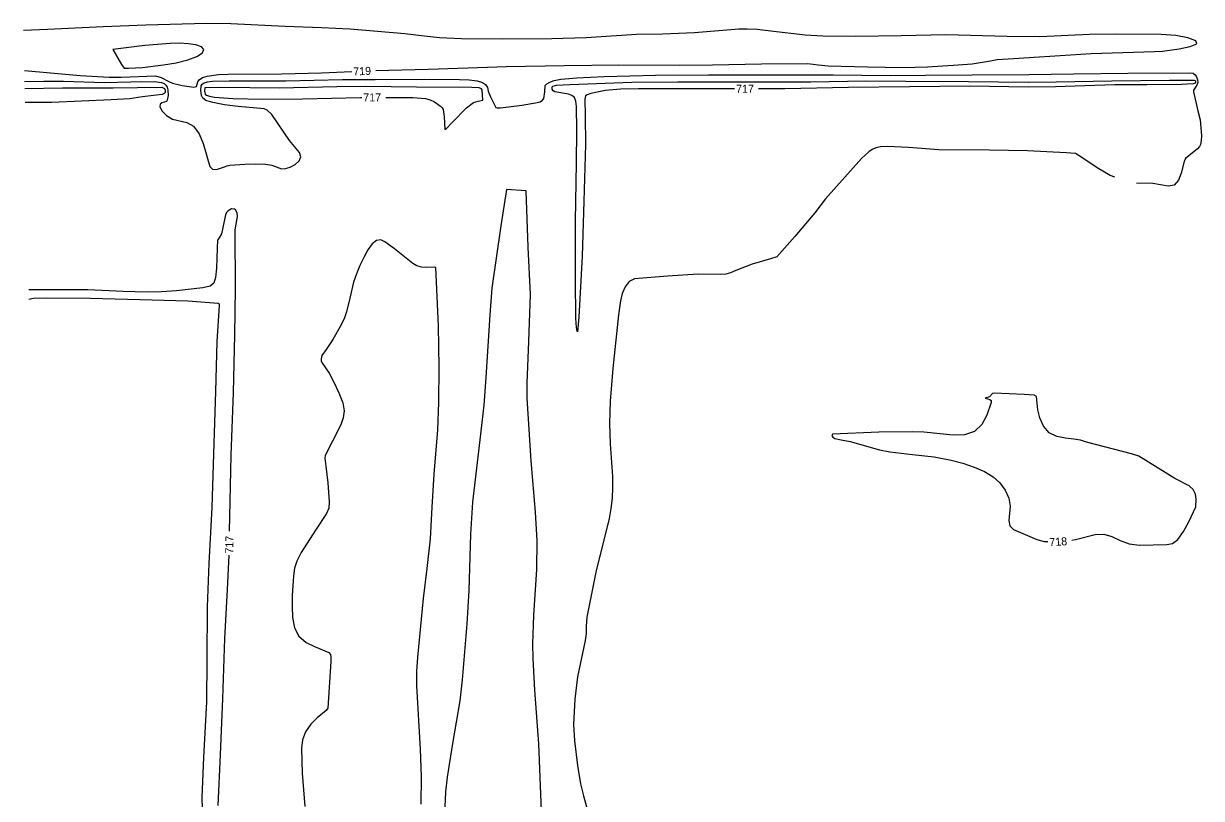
# Model space of a CAD drawing. Extents: x -310467766 to 17062430, y -322263100 to 8322522.
# Drawn here: x 1397523 to 1398112, y 573479 to 573867 of the extents above; entities that cross this region are included whole.
import ezdxf

# ---------------------------------------------------------------- set-up
doc = ezdxf.new("R2010")
doc.units = 0
doc.layers.add('DT_X_Contour_Minor', color=7, linetype='Continuous')
doc.layers.add('Level 19', color=7, linetype='Continuous')

msp = doc.modelspace()

# ---------------------------------------------------------------- linework, layer by layer
at = {"layer": 'DT_X_Contour_Minor'}
for points in [[(1397699.48, 573843.04), (1397725.75, 573843.69), (1397755.3, 573844.71), (1397764.75, 573845.01), (1397793.79, 573845.5), (1397821.02, 573845.9), (1397851.36, 573845.78), (1397867.89, 573845.89), (1397892.37, 573846.36), (1397915.31, 573846.63), (1397918.22, 573846.18), (1397920.58, 573845.83), (1397925.72, 573845.45), (1397945.29, 573844.83), (1397963, 573844.63), (1397975.33, 573844.98), (1397990.69, 573845.83), (1397997.71, 573846.46), (1398006.82, 573847.94), (1398010.21, 573848.53), (1398018.36, 573849.1), (1398031.26, 573849.87), (1398057.17, 573851.5), (1398088.83, 573852.55), (1398092.84, 573852.79), (1398101.06, 573853.93), (1398106.55, 573855.01), (1398109.94, 573856.38), (1398109.42, 573857.97), (1398105.53, 573859.49), (1398099.42, 573860.62), (1398092.15, 573861.15), (1398070.03, 573861.24), (1398056.32, 573861.13), (1398031.5, 573859.97), (1398015.11, 573860.04), (1397984.53, 573860.83), (1397962.23, 573860.43), (1397939.36, 573860.03), (1397922.95, 573860.26), (1397914.24, 573860.81), (1397896.95, 573862.74), (1397890.09, 573863.52), (1397885.23, 573863.82), (1397881.03, 573863.68), (1397858.88, 573861.93), (1397842.91, 573861.25), (1397829.91, 573861), (1397804.71, 573859.47), (1397787.57, 573858.89), (1397763.03, 573858.78), (1397742.33, 573858.95), (1397731.31, 573859.42), (1397722.43, 573860.36), (1397714.1, 573861.42), (1397686.62, 573863.82), (1397672.37, 573864.42), (1397654.18, 573865.01), (1397627.05, 573866.47), (1397614.95, 573866.55), (1397584.57, 573865.76), (1397563.28, 573864.94), (1397535.45, 573863.62), (1397523.43, 573863.03)], [(1397573.77, 573844.31), (1397575.93, 573844.21), (1397582.87, 573844.6), (1397593.34, 573845.83), (1397599.67, 573846.93), (1397605.5, 573848.36), (1397610.01, 573850.11), (1397612.81, 573851.95), (1397613.63, 573853.64), (1397612.37, 573854.95), (1397609.52, 573855.89), (1397605.74, 573856.45), (1397601.5, 573856.68), (1397596.66, 573856.58), (1397584.13, 573855.51), (1397568.04, 573853.56), (1397572.44, 573846.03), (1397573.77, 573844.31)], [(1397523.83, 573843), (1397551.67, 573840.54), (1397566.15, 573839.7), (1397572.23, 573839.81), (1397589.36, 573840.39), (1397592.23, 573839.52), (1397595.98, 573837.61), (1397597.96, 573836.72), (1397602.68, 573835.62), (1397608.54, 573834.8), (1397609.84, 573835.13), (1397610.19, 573836.31), (1397610.51, 573837.33), (1397611.28, 573838.47), (1397612.82, 573839.51), (1397615.27, 573840.28), (1397620.91, 573841.08), (1397625.75, 573841.27), (1397652.54, 573841.37), (1397672.35, 573841.91), (1397687.49, 573842.55)], [(1397523.94, 573837.63), (1397533.61, 573837.78), (1397543.38, 573837.74), (1397563.86, 573837.03), (1397577.12, 573837.33), (1397588.91, 573837.64), (1397592.39, 573837.1), (1397593.66, 573836.52), (1397594.61, 573835.72), (1397595.24, 573834.68), (1397595.6, 573833.45), (1397595.66, 573830.61), (1397595.19, 573828.23), (1397594.87, 573827.66), (1397593.64, 573827.23), (1397592.59, 573826.92), (1397591.71, 573826.23), (1397591.61, 573824.9), (1397592.71, 573822.82), (1397594.9, 573820.54), (1397597.91, 573818.77), (1397605.1, 573817.08), (1397608.44, 573815.17), (1397611.14, 573811.42), (1397613.17, 573806.55), (1397616.57, 573795.12), (1397617.88, 573793.72), (1397619.82, 573793.57), (1397623.88, 573794.96), (1397625.14, 573795.44), (1397626.6, 573795.69), (1397634.01, 573796.17), (1397639.53, 573796.37), (1397644.4, 573796.29), (1397647.49, 573795.77), (1397652.32, 573793.96), (1397654.36, 573794.05), (1397656.7, 573794.74), (1397659.18, 573796.1), (1397661.21, 573797.92), (1397662.09, 573799.97), (1397661.35, 573802.12), (1397656.45, 573808.12), (1397647.46, 573821.09), (1397645.28, 573823.17), (1397643.67, 573823.92), (1397630.72, 573825.1), (1397623.91, 573825.97), (1397618.04, 573827), (1397614.54, 573828.12), (1397612.98, 573829.32), (1397612.45, 573830.57), (1397612.07, 573833.14), (1397612.24, 573835.36), (1397612.71, 573836.22), (1397613.67, 573836.9), (1397615.31, 573837.38), (1397617.83, 573837.68), (1397626.25, 573837.88), (1397654.52, 573837.86), (1397682.93, 573838.54), (1397699.24, 573838.59), (1397723.67, 573838.67), (1397741.34, 573838.61), (1397746.17, 573838.41), (1397750.22, 573837.92), (1397752.85, 573837.07), (1397754.28, 573836.1), (1397755.41, 573834.52), (1397755.67, 573832.8), (1397756.85, 573829.93), (1397759.54, 573824.6), (1397760.23, 573824.42), (1397761.89, 573824.45), (1397772.57, 573825.81), (1397779.37, 573826.85), (1397781.63, 573827.46), (1397782.9, 573828.2), (1397783.46, 573829.1), (1397783.95, 573832.4), (1397784.25, 573835.55), (1397785.01, 573836.39), (1397786.44, 573837.29), (1397788.75, 573838.09), (1397792.02, 573838.69), (1397800.06, 573839.42), (1397813.71, 573840.01), (1397839.31, 573840.71), (1397865.81, 573840.92), (1397897.2, 573840.84), (1397928.21, 573840.87), (1397956.81, 573840.65), (1397974.33, 573840.76), (1397997.62, 573840.99), (1398025.93, 573841.12), (1398048.26, 573841.43), (1398075.52, 573841.77), (1398106.86, 573841.99), (1398108.06, 573841.67), (1398109.06, 573840.99), (1398109.87, 573839.85)], [(1398109.87, 573839.85), (1398110.38, 573838.43), (1398110.44, 573837), (1398109.99, 573835.74), (1398108.31, 573833.21), (1398108.33, 573832.38), (1398110.5, 573822.94), (1398111.68, 573818.42), (1398112.27, 573810.66), (1398112.17, 573807.9), (1398111.77, 573806.11), (1398111.27, 573805.04), (1398110.28, 573803.85), (1398104.26, 573799.01), (1398103.65, 573797.54), (1398102.17, 573791.76), (1398100.76, 573788.17), (1398098.63, 573785.7), (1398095.67, 573785.19), (1398088.01, 573786.66), (1398079.86, 573786.74)], [(1397524.01, 573834.09), (1397542.84, 573834.41), (1397568.29, 573834.44), (1397592.55, 573834.72), (1397593.86, 573834.16), (1397594.26, 573833.23), (1397594.23, 573832.07), (1397593.8, 573831.51), (1397592.74, 573831.08), (1397588.39, 573830.6), (1397582.9, 573829.89), (1397576.4, 573828.93), (1397567.29, 573828.43), (1397537.58, 573827.12), (1397532.63, 573827), (1397524.15, 573827.14)], [(1397704.48, 573829.63), (1397718, 573829.66), (1397724.34, 573829.1), (1397726.75, 573828.43), (1397728.84, 573827.44), (1397731.92, 573825.28), (1397732.77, 573824.47), (1397733.24, 573823.58), (1397733.63, 573820.09), (1397733.96, 573813.61), (1397734.45, 573813.83), (1397737.68, 573817.12), (1397744.93, 573824.49), (1397748.3, 573827.02), (1397750.7, 573827.79), (1397753.02, 573828.28), (1397752.73, 573833.44), (1397752.42, 573833.87), (1397751.17, 573834.43), (1397747.57, 573834.64), (1397719.86, 573834.69), (1397694.59, 573835.1), (1397680.06, 573834.92), (1397651.27, 573834.27), (1397621.98, 573834.6), (1397614.12, 573834.4), (1397613.87, 573832.75), (1397614.24, 573831.19), (1397614.88, 573830.7), (1397616.31, 573830.24), (1397618.87, 573829.82), (1397628.15, 573829.15), (1397642.67, 573828.82), (1397662.83, 573828.95), (1397691.93, 573829.59), (1397692.48, 573829.59)], [(1397878.89, 573833.94), (1397874.82, 573833.94), (1397857.2, 573833.98), (1397830.81, 573833.96), (1397821.94, 573833.82), (1397814.16, 573833.01), (1397807.01, 573831.63), (1397805.16, 573830.99), (1397804.36, 573830.36), (1397804.05, 573828.71), (1397804.16, 573820.44), (1397804.27, 573806.07), (1397803.5, 573777.68), (1397802.64, 573750.2), (1397801.05, 573719.7), (1397800.4, 573712.51), (1397800.12, 573712.77), (1397799.79, 573714.54), (1397799.53, 573719.34), (1397799.39, 573738.61), (1397799.35, 573767.89), (1397799.78, 573796.83), (1397800.04, 573813.3), (1397799.82, 573825.09), (1397799.5, 573827.67), (1397798.78, 573829.51), (1397797.49, 573830.62), (1397795.8, 573831.2), (1397789.01, 573832.35), (1397788.12, 573832.96), (1397787.64, 573833.68), (1397787.61, 573834.87), (1397788.01, 573835.24), (1397789.88, 573835.69), (1397796.47, 573836.07), (1397827.44, 573837.18), (1397850.52, 573837.39), (1397883.7, 573837.44), (1397917.03, 573837.37), (1397944.52, 573837.89), (1397964.55, 573837.69), (1397995.75, 573837.51), (1398025.92, 573837.2), (1398039.56, 573837.39), (1398067.42, 573837.88), (1398096.24, 573838.25), (1398108.71, 573838.28), (1398109.25, 573837.83), (1398109.35, 573837.11), (1398109.09, 573836.76), (1398108.13, 573836.45), (1398102.22, 573836.06), (1398085, 573835.96), (1398069.03, 573835.85), (1398053.94, 573835.34), (1398039.27, 573834.83), (1398025.71, 573834.82), (1397996.67, 573835.18), (1397966.24, 573834.85), (1397935.86, 573834.59), (1397904.01, 573833.96), (1397890.89, 573833.95)], [(1398068.9, 573789.7), (1398066.71, 573790.64), (1398060.22, 573794.34), (1398051.95, 573799.88), (1398049.27, 573801.62), (1398044.7, 573801.94), (1398025.24, 573802.94), (1398006.28, 573803.19), (1397981.04, 573803.34), (1397974.41, 573803.86), (1397965.88, 573804.66), (1397955.29, 573805.13), (1397951.77, 573804.92), (1397949.43, 573804.38), (1397947.69, 573803.56), (1397946.04, 573802.47), (1397942.28, 573799.03), (1397924.25, 573778.94), (1397919.07, 573771.99), (1397908.97, 573760.08), (1397900.06, 573749.97), (1397896.82, 573748.94), (1397887.71, 573746.18), (1397879.48, 573743.11), (1397876.87, 573741.98), (1397874.56, 573741.29), (1397872.03, 573741.09), (1397860.7, 573741.22), (1397845.28, 573740.3), (1397828.84, 573738.96), (1397826.12, 573737.53), (1397824.1, 573734.94), (1397822.7, 573731.56), (1397821.77, 573727.97), (1397820.77, 573720.96), (1397817.99, 573694.05), (1397816.73, 573677.82), (1397816.33, 573666.63), (1397816.66, 573656.36), (1397817.8, 573640.16), (1397817.91, 573634.59), (1397817.65, 573629.23), (1397817.04, 573624.06), (1397816.1, 573619.07), (1397809.54, 573592.31), (1397805.07, 573569.86), (1397804.62, 573565.34), (1397804.64, 573561.56), (1397804.15, 573558.05), (1397800.37, 573539.96), (1397799.02, 573528.85), (1397798.43, 573516.21), (1397798.84, 573507.96), (1397800.4, 573495.64), (1397801.93, 573486.41), (1397803.38, 573480.42), (1397809.49, 573458.2)], [(1397782.42, 573473.04), (1397781.04, 573506.43), (1397779.06, 573533.31), (1397778.13, 573549.13), (1397778.05, 573556.42), (1397778.6, 573570.83), (1397780.09, 573593.66), (1397780.18, 573608.11), (1397779.34, 573622.21), (1397777.18, 573647.99), (1397775.11, 573679.32), (1397775.12, 573686.77), (1397775.95, 573707.65), (1397776.93, 573731.07), (1397775.73, 573754.81), (1397774.75, 573782.91), (1397764.81, 573783.52), (1397762.03, 573765.4), (1397757.57, 573734.24), (1397756.49, 573720.95), (1397754.47, 573689.67), (1397753.53, 573675.82), (1397751.54, 573658.49), (1397747.82, 573627.25), (1397746.8, 573611.26), (1397745.98, 573583.18), (1397745.03, 573566.37), (1397742.77, 573538.5), (1397741.48, 573527.91), (1397737.91, 573506.69), (1397735.13, 573489.78), (1397734.41, 573482.53), (1397733.61, 573463.94)], [(1397626.44, 573612.81), (1397626.71, 573627.53), (1397627.21, 573650.74), (1397628.31, 573682.07), (1397629.03, 573710.93), (1397629.42, 573733.89), (1397629.15, 573763.36), (1397629.63, 573766.25), (1397630.38, 573770.01), (1397630.18, 573772), (1397629.43, 573773.37), (1397628.84, 573773.76), (1397627.31, 573773.84), (1397625.66, 573772.98), (1397624.94, 573772.12), (1397624.4, 573770.89), (1397622.36, 573761.49), (1397621.2, 573759.35), (1397620.32, 573758.18), (1397620.16, 573754.19), (1397619.85, 573744.29), (1397619.42, 573739.67), (1397618.55, 573736.81), (1397616.64, 573735.33), (1397612.99, 573734.49), (1397599.96, 573732.92), (1397592.35, 573732.38), (1397585.22, 573732.19), (1397573.16, 573732.53), (1397555.55, 573733.45), (1397530.53, 573733.43), (1397526.05, 573733.47)], [(1397722.23, 573476.31), (1397722.38, 573489.92), (1397721.89, 573503.78), (1397720.09, 573535.44), (1397720.11, 573542.68), (1397720.54, 573549.75), (1397723.43, 573579.12), (1397725.13, 573594.1), (1397726.83, 573608.97), (1397727.71, 573624.78), (1397728.72, 573641.3), (1397730.45, 573663.52), (1397730.96, 573677.13), (1397731.25, 573694.77), (1397730.87, 573715.49), (1397729.45, 573744.58), (1397728.95, 573744.8), (1397724.67, 573744.55), (1397722.36, 573744.78), (1397720.06, 573745.44), (1397718, 573746.63), (1397708.89, 573753.9), (1397704.08, 573757.38), (1397701.95, 573758.36), (1397699.87, 573758.14), (1397697.73, 573756.38), (1397695.58, 573753.38), (1397693.5, 573749.66), (1397691.55, 573745.64), (1397689.82, 573741.49), (1397688.42, 573737.3), (1397686.56, 573729.27), (1397684.95, 573722.46), (1397683.81, 573719.35), (1397682.25, 573716.01), (1397677.98, 573708.53), (1397674.65, 573703.59), (1397672.47, 573700.6), (1397672.13, 573698.94), (1397672.17, 573698), (1397672.49, 573697.07), (1397676.15, 573691.73), (1397678.58, 573687.29), (1397681.09, 573682.01), (1397682.96, 573676.94), (1397683.66, 573672.88), (1397683.25, 573669.43), (1397681.96, 573665.89), (1397677.93, 573657.72), (1397674.23, 573650.61), (1397674.05, 573649.33), (1397674.56, 573645.22), (1397675.61, 573637), (1397676.23, 573627.5), (1397675.97, 573624.36), (1397674.94, 573621.69), (1397669.41, 573613.35), (1397662.17, 573602.17), (1397660.02, 573597.86), (1397658.9, 573594.2), (1397658.33, 573590.38), (1397657.7, 573580.57), (1397657.65, 573575.05), (1397657.89, 573569.57), (1397658.84, 573564.52), (1397661.02, 573560.3), (1397664.63, 573557.18), (1397668.84, 573555.05), (1397676.02, 573552.16), (1397676.82, 573551.16), (1397677.04, 573549.97), (1397676.98, 573547.63), (1397675.62, 573524.22), (1397674.64, 573523.18), (1397670.17, 573519.39), (1397666.96, 573516.22), (1397664.29, 573512.5), (1397662.85, 573508.49), (1397662.39, 573504.32), (1397662.63, 573491.73), (1397663.34, 573483.4), (1397664.11, 573475.21)], [(1397526.14, 573728.83), (1397528.38, 573729.18), (1397535.11, 573729.49), (1397556.82, 573729.31), (1397587.71, 573728.48), (1397605.55, 573727.91), (1397620.74, 573726.79), (1397621.15, 573726.48), (1397621.25, 573725.57), (1397619.97, 573707.62), (1397619.3, 573682.61), (1397618.59, 573656.71), (1397617.59, 573624.64), (1397616.1, 573596.58), (1397615.24, 573574.91), (1397615.09, 573548.63), (1397614.82, 573527.53), (1397613.35, 573499.58), (1397612.49, 573479.81), (1397613.24, 573455.05)], [(1398047.4, 573608.33), (1398049.26, 573608.64), (1398059.11, 573611.15), (1398063.44, 573611.32), (1398067.51, 573610.07), (1398071.63, 573608.1), (1398076.17, 573606.44), (1398081.33, 573605.82), (1398094.89, 573606.11), (1398097.77, 573606.59), (1398100.44, 573608.55), (1398103.24, 573612.55), (1398105.89, 573617.43), (1398109.52, 573625), (1398109.6, 573628.75), (1398109.27, 573631.31), (1398108.19, 573633.69), (1398106.05, 573635.48), (1398098.9, 573639.16), (1398080.99, 573650.22), (1398077.38, 573651.47), (1398054.79, 573657.28), (1398051.74, 573658.2), (1398048.45, 573658.85), (1398044.39, 573659.3), (1398040.03, 573660.11), (1398036.12, 573661.96), (1398033.24, 573665.29), (1398031.41, 573669.42), (1398030.48, 573673.43), (1398029.85, 573680.13), (1398028.68, 573680.8), (1398023.69, 573681.14), (1398008.69, 573681.82), (1398007.81, 573681.53), (1398006.31, 573679.95), (1398004.1, 573679.33), (1398006.56, 573678.56), (1398007.19, 573678.1), (1398007.13, 573677.03), (1398004.92, 573670.7), (1398002.49, 573666.18), (1397998.8, 573662.57), (1397993.77, 573660.91), (1397988.1, 573660.76), (1397973.54, 573662.32), (1397967.6, 573662.5), (1397950.99, 573662.2), (1397927.91, 573661.27), (1397927.55, 573660.64), (1397927.99, 573659.85), (1397929.01, 573659.18), (1397932.11, 573658.52), (1397936.73, 573657.56), (1397951.4, 573653.46), (1397956.49, 573652.47), (1397967.74, 573651.08), (1397978.73, 573649.95), (1397987.12, 573648.22), (1397992.91, 573646.71), (1397998.72, 573644.84), (1398003.83, 573642.64), (1398008.11, 573640.02), (1398011.56, 573636.92), (1398014.18, 573633.28), (1398015.9, 573629.31), (1398016.61, 573625.28), (1398016.03, 573618.03), (1398016.45, 573615.37), (1398018.32, 573613.59), (1398029.97, 573608.64), (1398033.59, 573607.69), (1398035.42, 573607.56)], [(1397620.73, 573475.58), (1397621.96, 573500.99), (1397623.02, 573529.07), (1397624.01, 573559.09), (1397625.32, 573583.67), (1397626.17, 573600.82)]]:
    msp.add_lwpolyline(points, dxfattribs=at)

# ---------------------------------------------------------------- texts
at = {"layer": 'Level 19'}
for s, rotation, p in [('719', 2.41788, (1397688.31, 573840.58)), ('717', 0.05157, (1397879.63, 573831.94)), ('717', 0.14897, (1397693.23, 573827.6)), ('717', 88.94024, (1397628.23, 573601.52)), ('718', 3.53515, (1398036.33, 573605.25))]:
    msp.add_text(s, height=4, rotation=rotation, dxfattribs=at).set_placement(p)

doc.saveas('drawing.dxf')
